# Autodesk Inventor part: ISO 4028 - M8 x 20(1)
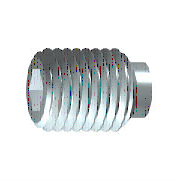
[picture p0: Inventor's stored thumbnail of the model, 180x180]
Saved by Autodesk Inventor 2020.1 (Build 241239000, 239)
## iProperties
Created: 2019-01
Part Number: ISO 4028 - M8 x 20(1)
Material: Edelstahl, 440C
Description: Innensechskant-Gewindestifte mit Zapfen
Document SubType Name: Modeling
Standard: ISO 4028
Designer: lutzd
Standard Revision: Third edition 2003-12-01
Standards Organization: ISO
Language: de-DE
Size Designation: M8 x 20
Categories: <MemberInstance><Categories><Category DisplayName="Verbindungselemente" InternalName="e4da775c-781d-43d5-af7c-5136215cf5a6" Mnemonic="FSTN"><Category DisplayNam
Mass: 6.18644 g
Surface Area: 6.12331 cm^2
Volume: 0.79825 cm^3
Density: 7.75 g/cm^3
Appearance: Halbpoliert
IsCustomPart: 0
Author: lutzd
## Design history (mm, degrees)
sketch "Skizze1"
  geometry: L1 (0, 0)-(13.667, 0); L2 (20, 2.309)-(20, 4); L3 (20, 4)-(4, 4); L4 (20, 2.309)-(15, 2.309); L5 (15, 2.309)-(13.667, 0); L6 (0, -0.8)-(0, 4.8) reference; L7 (0, 2.75)-(0, 0); L8 (0, 2.75)-(4, 2.75); L9 (4, 2.75)-(4, 4)
  constraints: 17 end point, 3 parallel, 3 perpendicular, 1 collinear, 1 point on line
  dimensions: "d0" = 5 distance of L2.start L4.end (= INTI); "d1" = 60 deg angle of L5 L1; "d2" = 8 diameter of L3 L1 (= NND); "d3" = 4.6188 diameter of L4 L1 (= 1.1547 x SW); "d5" = 20 distance from line of L2 L7.start (= NLG); "d7" = 5.5 diameter of L7.start L1 (= SPD); "d14" = 4 distance of L7.start L8.end (= ZLG)
revolve "Körper" sketch "Skizze1" stored, may be unused: angle "d6" = 90 deg
sketch "Skizze2"
  geometry: L1 (-1.155, 2)-(1.155, 2); L2 (1.155, 2)-(2.309, 0); L3 (2.309, 0)-(1.155, -2); L4 (1.155, -2)-(-1.155, -2); L5 (-1.155, -2)-(-2.309, 0); L6 (-2.309, 0)-(-1.155, 2); A1 r 2.309 centre (0, 0) between (-1.155, 2) and (1.155, 2) reference; 2 further points
  constraints: 12 end point, 2 point on circle, 1 coincident, 1 horizontal, 11 other
extrude "Loch" join sketch "Skizze2" taper "d10" = 0 deg; stored distance "d21" = 10
workaxis "Work Axis1"
workplane "Work Plane1"
body "Solid1"
chamfer "Fase1" distance "d8" = 0.76681 (computed from NND, GD1, FAWI); stored, may be unused: angle "d9" = 45 deg (= FAWI), second distance "d30" = 0.76681 (computed from NND, GD1, FAWI)
feature "Gewinde" dims "d12" = 16 (= NLG - ZLG), "d13" = 0
chamfer "Fase2" distance "d15" = 1.25 (computed from NND, SPD, FAWI1); stored, may be unused: angle "d16" = 45 deg (= FAWI1), second distance "d31" = 1.25 (computed from NND, SPD, FAWI1)
other parameters: "NND" = 8 [user parameter; used in 5 equation terms], "NLG" = 20 [user parameter; used in 2 equation terms], "INTI" = 5 [user parameter; used in 1 equation term], "FAWI" = 45 deg [user parameter; used in 3 equation terms], "SW" = 4 [user parameter; used in 2 equation terms], "GD1" = 6.46637 (= THREADDIA - 1.2269 x PTC) [user parameter; used in 2 equation terms], "d4" = 0, "FAWI1" = 45 deg [user parameter; used in 3 equation terms], "SPD" = 5.5 [user parameter; used in 3 equation terms], "ZLG" = 4 [user parameter; used in 2 equation terms], "d32" = 0, "d33" = 0, "GUL" = 0.76681 (= 0.61345 x PTC) [user parameter], "TPU" = 8 (computed from PTC) [user parameter], "TOA" = 30 deg [user parameter], "THREADDIA" = 8 [user parameter; used in 1 equation term], "PTC" = 1.25 [user parameter; used in 4 equation terms], "GAL" = 0.76681 (= 0.61345 x PTC) [user parameter], "E0" = 4.62 (= 1.155 x SW) [user parameter]
